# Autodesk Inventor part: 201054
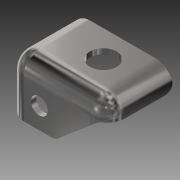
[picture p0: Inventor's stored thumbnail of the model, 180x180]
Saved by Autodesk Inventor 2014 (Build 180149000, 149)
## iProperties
Created: 2007-10
Part Number: 201054
Document SubType Name: Modeling
Designer: TH
Density: 7.85 g/cm^3
Mass: 44.1035 g
Surface Area: 50.9461 cm^2
Volume: 5.61828 cm^3
Material: Steel
Description: CORNER BRACKET
Appearance: Steel - Polished
Component Category: Lower Component
Author: TH
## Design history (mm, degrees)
sketch "Sketch1"
  geometry: L1 (-24.142, 15.787)-(24.141, 15.787); L2 (24.141, 15.787)-(24.141, -15.787); L3 (24.141, -15.787)-(-24.142, -15.787); L4 (-24.142, -15.787)-(-24.142, 15.787); 1 further point
  constraints: 8 end point, 2 parallel, 1 horizontal, 1 perpendicular
  dimensions: "d0" = 31.574 distance of L3.end L1.start; "d1" = 48.283 distance of L1.start L1.end; "d2" = 24.1415 distance from line of point (0, 0) L4 (= 0.5 x d1); "d3" = 15.787 distance from line of point (0, 0) L1 (= 0.5 x d0)
extrude "Extrusion1" new body sketch "Sketch1" distance "d4" = 26.136; taper "d5" = 0 deg
fillet "Fillet1" dims "d6" = 8.5
shell "Shell1" dims "d7" = 2.5
sketch "Sketch2"
  geometry: L1 (0, 23.074)-(-17.636, 23.074) reference; L2 (-17.636, 23.074)-(-17.636, 0) reference; L3 (-17.636, -0.926)-(-0.636, -0.926); L4 (-0.636, -0.926)-(-0.636, 23.074); L5 (-0.636, 23.074)-(-17.636, 23.074); L6 (-17.636, 23.074)-(-17.636, -0.926); 1 further point
  constraints: 8 end point, 2 parallel, 2 point on line, 1 horizontal, 1 perpendicular
  dimensions: "d8" = 17 distance of L3.start L3.end; "d9" = 24 distance from line of L3 L1.start
extrude "Extrusion2" cut sketch "Sketch2" stored distance "d10" = 26.136; taper "d11" = 0 deg
sketch "Sketch3"
  geometry: L1 (39.783, 8.5)-(39.783, 9.136) reference; L2 (39.783, 9.136)-(34.783, 9.136); L3 (34.783, 9.136)-(14.783, 26.136); L4 (0, 26.136)-(31.283, 26.136) reference; L5 (39.783, 9.136)-(39.783, 26.136); L6 (39.783, 26.136)-(14.783, 26.136); 1 further point
  constraints: 8 end point, 2 perpendicular, 2 point on line, 1 collinear
  dimensions: "d12" = 5 distance of L1.end L2.end; "d13" = 20 horizontal distance of L3.end L2.end
extrude "Extrusion3" cut sketch "Sketch3" stored distance "d14" = 26.136; taper "d15" = 0 deg
fillet "Fillet2" dims "d16" = 4
sketch "Sketch4"
  geometry: L1 (0.262, -15.787)-(-2.329, -15.787) reference; L2 (0.262, -15.787)-(15.641, -15.787) reference; L3 (-15.642, -15.787)-(15.641, -15.787) reference; L4 (-15.642, -15.787)-(-2.329, -15.787) reference; L5 (-24.142, 11.787)-(-24.142, 13.951) reference; L6 (-24.142, 11.787)-(-24.142, -4.213) reference; L7 (-24.142, -4.213)-(-24.142, -7.287) reference; L8 (-24.142, 13.951)-(-24.142, -7.287) reference; 2 further points
  dimensions: "d17" = 27.606 distance from line of point (3.464, 2.911) L8; "d18" = 18.698 distance from line of L3 point (3.464, 2.911)
hole "Hole1" sketch "Sketch4" at (3.464, 2.911) diameter "d19" = 12.8; stored, may be unused: countersink angle "d23" = 90 deg, drill point angle "d25" = 118 deg; dims "d20" = 6, "d21" = 4, "d22" = 2, "d24" = 8
sketch "Sketch5"
  geometry: L1 (-8.5, -2.077)-(-8.5, -0.636) reference; L2 (12.706, 8.5)-(25.506, 8.5) reference; L3 (0, 8.5)-(31.283, 8.5) reference; L4 (31.283, 8.5)-(0, 8.5) reference; 2 further points
  dimensions: "d26" = 15.663 distance from line of point (7.163, -7.48) L1; "d27" = 15.98 distance from line of L3 point (7.163, -7.48)
hole "Hole2" sketch "Sketch5" at (7.163, -7.48) diameter "d28" = 8; stored, may be unused: countersink angle "d32" = 90 deg, drill point angle "d34" = 118 deg; dims "d29" = 6, "d30" = 4, "d31" = 2, "d33" = 8
body "Solid1"
node "Projected Loop1"
node "Projected Loop2"
node "Projected Loop3"
